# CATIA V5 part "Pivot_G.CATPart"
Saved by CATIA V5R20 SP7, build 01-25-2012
Part number: Pivot_G
Bounding box of the stored display mesh (mm): x 147.5 to 152.5, y -2.5 to 2.5, z -6 to 6
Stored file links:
  D:\IFMA\COURS\2A\projet balance IAO\catia\Pivot_G.CATPart
  D:\IFMA\COURS\2A\projet balance IAO\catia\Ass_projet_balance.CATProduct
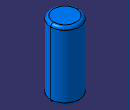
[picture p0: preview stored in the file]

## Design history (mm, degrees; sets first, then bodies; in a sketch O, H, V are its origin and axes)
Set1
  Plane1 "Plan_plateau_droit": linked copy from another document
  Point1 "Point.G": linked copy from another document
Body1 (main body)
  Sketch1 on Plane1, origin (0, 0, 0), H (1, 0, 0), V (0, 1, 0)
    circle A1 centre (150, 0) radius 2.5
    point P1 (150, 0)
    reference projected point E1 (150, 0) from Point1
    radius A1 = 2.5
    coincidence: P1 E1
  Pad1: profile Sketch1, direction (0, 0, 1), length 6, mirrored extent
  Fillet1: radius 0.5, on edge [face of Pad1 from Sketch1.A1 | end face of Pad1]; edge [start face of Pad1 | face of Pad1 from Sketch1.A1]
